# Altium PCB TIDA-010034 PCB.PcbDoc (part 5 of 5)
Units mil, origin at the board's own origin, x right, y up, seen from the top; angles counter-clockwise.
Board outline 4497.63 x 4881.81 mil, 4 copper layers (Top Layer, Signal Layer 1, Signal Layer 2, Bottom Layer), stack 62.18 mil thick; 483 components, 240 nets, 1255 pads, 589 vias.
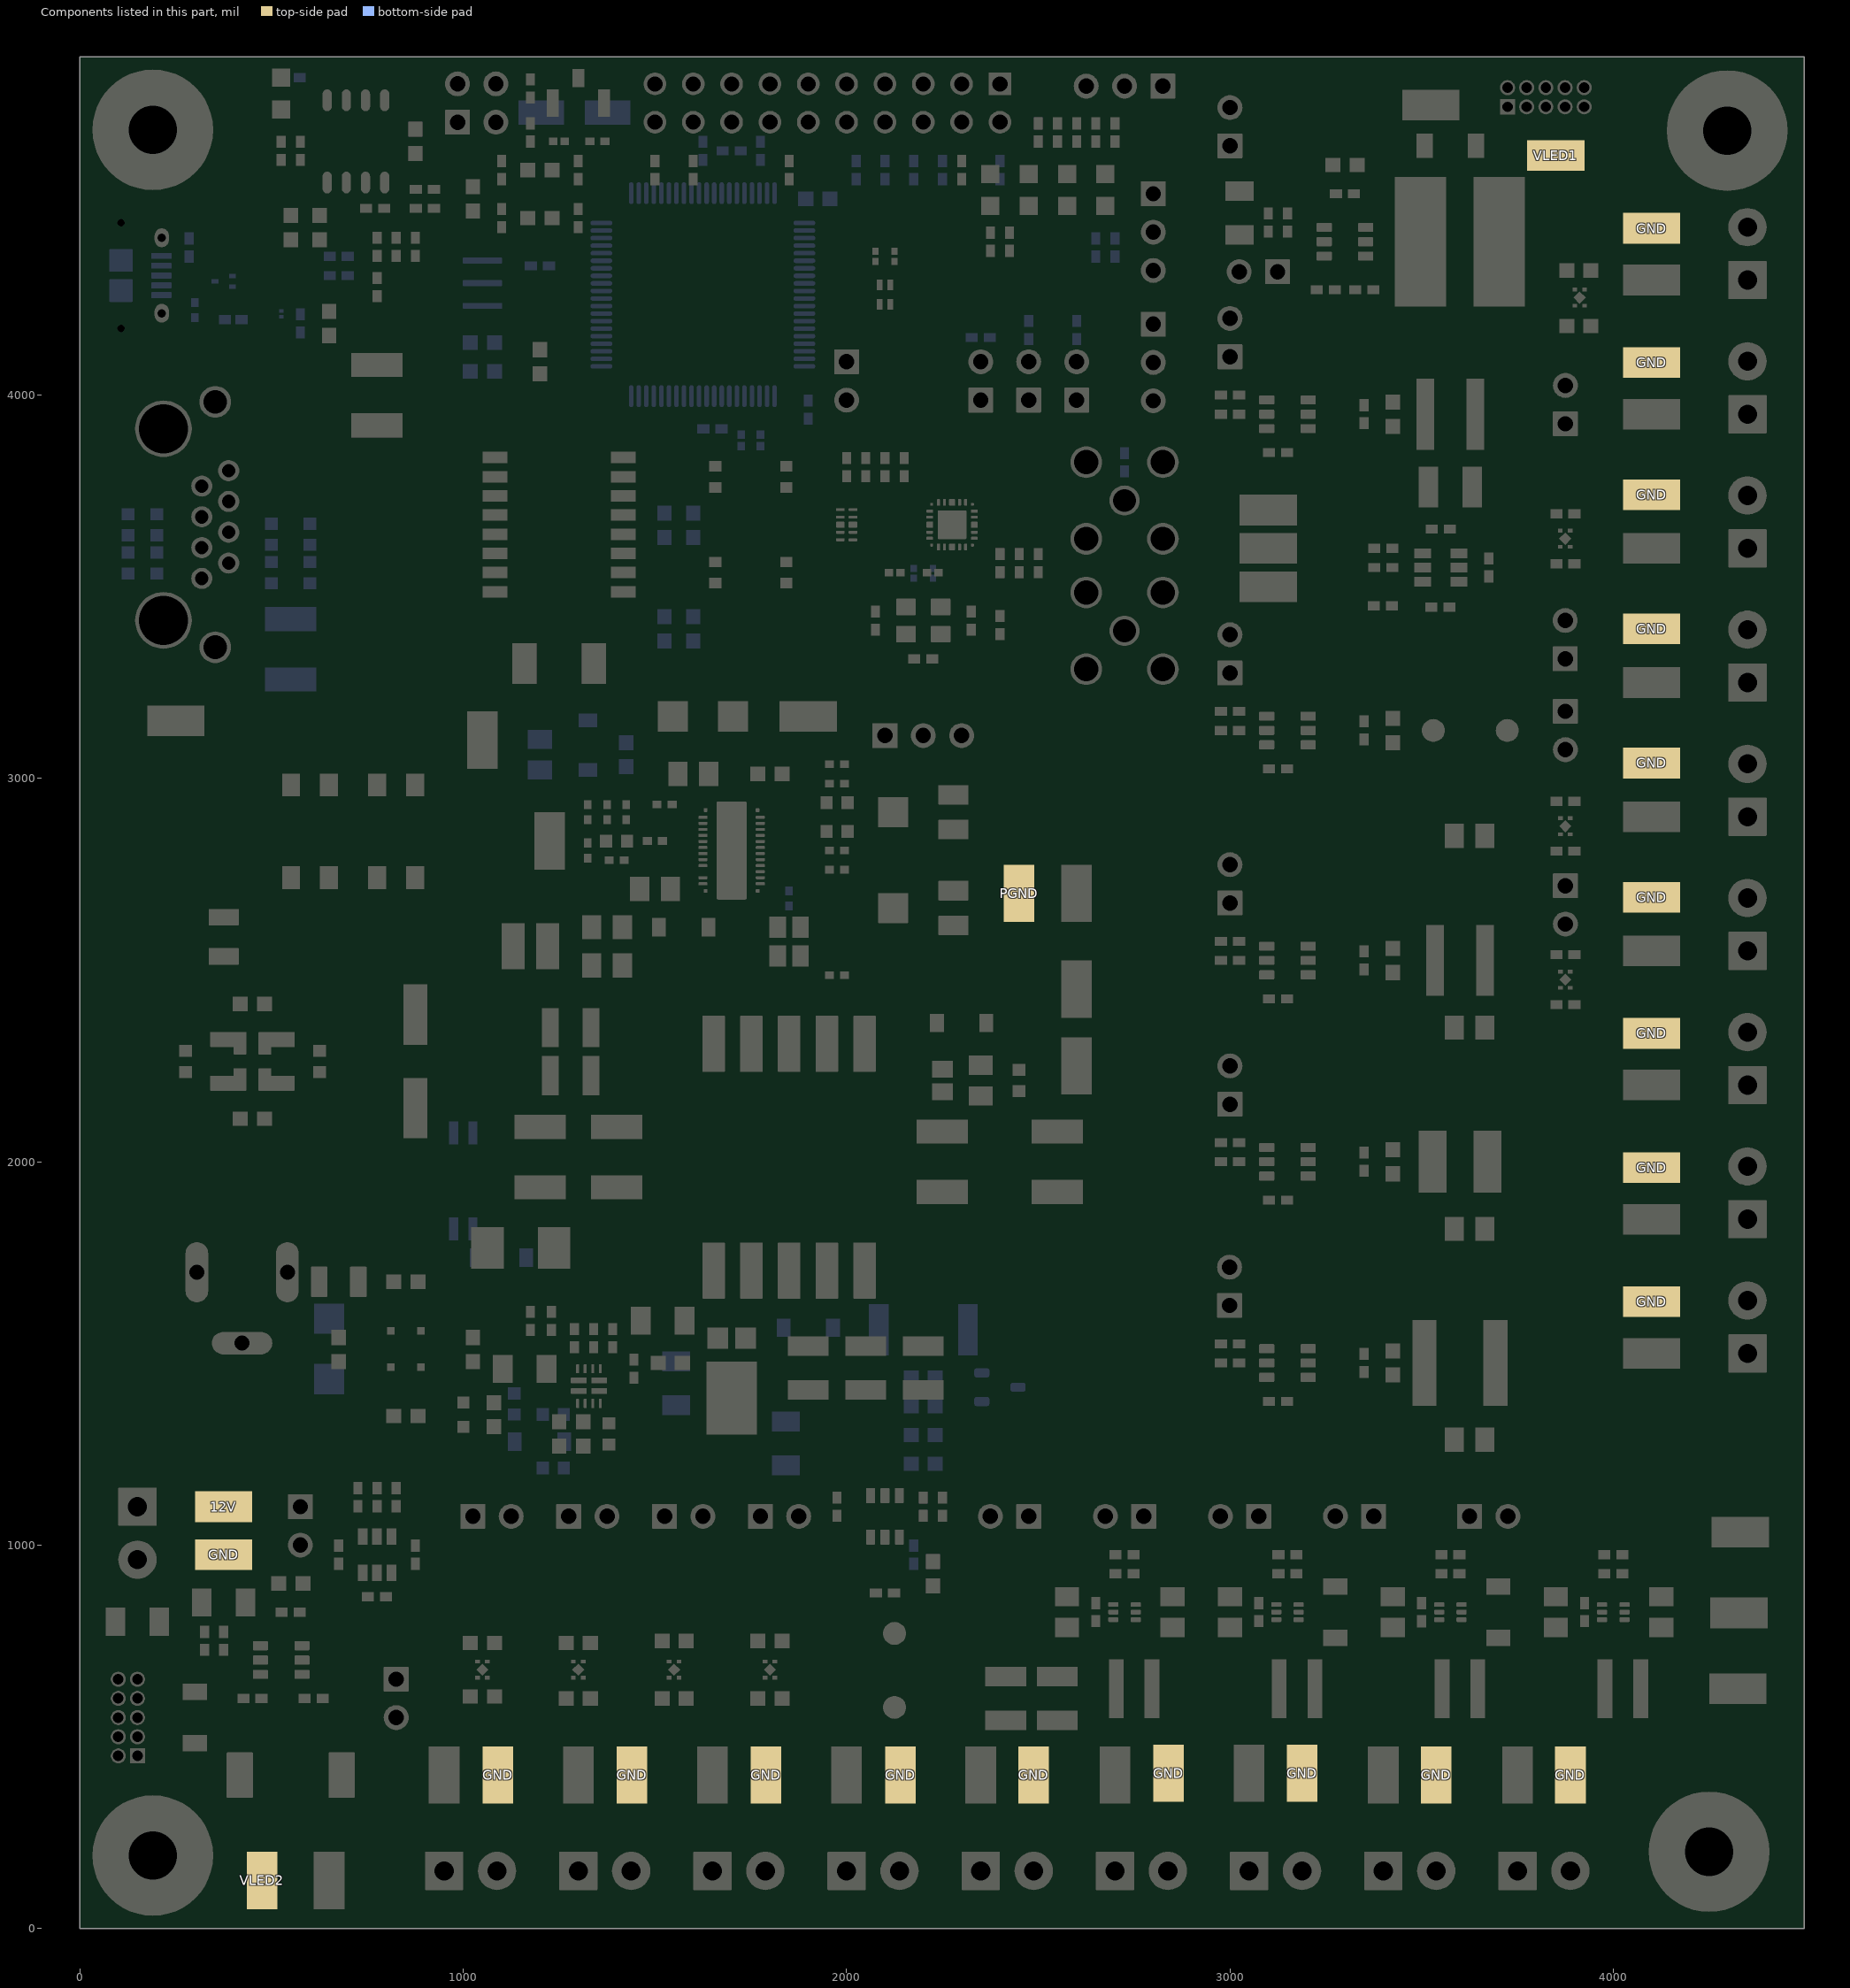
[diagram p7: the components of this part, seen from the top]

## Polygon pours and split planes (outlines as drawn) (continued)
VDD1_1.5V_Img on Signal Layer 2 "Top Layer-No Net 20" (solid, remove dead copper, pour order 568): 4029.76,2622 4410,2622 4420.25,2611.75 4420.25,2502 4410,2492 4029.25,2492 4015,2506.25 4015,2606.87
VDD1_2.8V_Img on Signal Layer 2 "Top Layer-No Net 16" (solid, pour order 566): 3880,2900 3890,2890 3950,2890 3960,2880 4000,2880 4050,2830 4410,2830 4420,2840 4420,2950 4410,2960 3890,2960 3880,2950
NetC76_1 on Signal Layer 2 "Bottom Layer-No Net 2" (solid, pour order 550): 2128,988 2138,978 2138,957 2138,678 2128,668 2068,668 2058,678 2058,978 2068,988
NetC39_1 on Signal Layer 2 "Bottom Layer-No Net 2" (solid, pour order 546): 3240,3980 3250,3990 3580,3990 3590,3980 3590,3920 3580,3910 3250,3910 3240,3920
NetC46_1 on Signal Layer 2 "Bottom Layer-No Net 2" (solid, pour order 536): 3240,3155 3250,3165 3580,3165 3590,3155 3590,3095 3580,3085 3250,3085 3240,3095
EARTH_GND on Signal Layer 2 "Signal Layer 1-No Net 2" (solid, remove dead copper, pour order 352): 30,3980 100,4050 465,4050 553.19,3961.81 878.19,3961.81 930,3910 1215,3910 1215,3250 1195,3230 105,3230 30,3305
VDD1_5V on Signal Layer 2 "Signal Layer 2-No Net 9" (solid, pour order 492): 3560,4132 3580,4152 4178,4152 4190,4140 4190,4030 4210,4010 4410,4010 4420,4000 4420,3850 4410,3840 3687,3840 3687,4020 3580,4020 3560,4040
VDD1_3.3VA on Signal Layer 2 "Top Layer-No Net 20" (solid, remove dead copper, pour order 490): 4029.76,4372 4410,4372 4420.25,4361.75 4420.25,4252 4410,4242 4029.25,4242 4015,4256.25 4015,4356.87
VDD1_3.3V on Signal Layer 2 "Signal Layer 2-No Net" (solid, pour order 482): 20 vertices, not listed, extent 3600,3130 4420,3450
VDD2_5V on Signal Layer 2 "Signal Layer 2-No Net 7" (solid, pour order 444): 17 vertices, not listed, extent 2230,30 2590,600
VDD2_5V on Signal Layer 2 "Signal Layer 2-No Net 5" (solid, pour order 442): 2720,1120 2730,1130 2850,1130 2960,1240 3950,1240 3970,1220 3970,1030 3960,1020 2730,1020 2720,1030
VDD2_5V on Signal Layer 2 "Signal Layer 2-No Net 4" (solid, pour order 438): 970,1140 990,1160 1849,1160 1869,1140 1869,990 1849,970 990,970 970,990
GND on Signal Layer 2 "Signal Layer 2-No Net 6" (solid, remove dead copper, pour order 356): 0,4881.81 0,4157 61,4096 514,4096 580.34,4029.66 890.34,4029.66 980,3940 1285,3940 1285,3925 1285,3250 1305,3230 2855,3230 2902,3277 2902,4842.81 2863,4881.81
PGND on Signal Layer 2 "Signal Layer 2-PGND" (solid, remove dead copper, pour order 354): 30,3065 30,2027 93,1964 2666,1964 2872,2170 2872,3128 2815,3185 150,3185
VLED2 on Signal Layer 2 "Bottom Layer-No Net 8" (solid, remove dead copper, pour order 312): 684.71,775.29 684.71,54.71 665,35 410,35 367,78 367,270 202,435 60,435 30.26,464.74 30,525 30,820 90,880 580,880
12V on Signal Layer 2 "Signal Layer 2-No Net 2" (solid, remove dead copper, pour order 302): 27 vertices, not listed, extent 35,1025 3171,4881
VDD2_3.3V on Signal Layer 2 "Signal Layer 2-No Net 1" (solid, remove dead copper, pour order 298): 2615,770 2625,780 2893.39,780 2901,771.16 2901,40 2891,30 2625,30 2615,40
VDD2_1.5V_Img on Signal Layer 2 "Top Layer-No Net 5" (solid, remove dead copper, pour order 288): 1884,189 1884,39 1892.91,30.09 1987.74,30.26 2052.95,29.95 2063,40 2063,235 2038,260 1853,445 1853,640 1843,650 1753.47,650 1743,639.53 1743,330
VDD2_2.8V_Img on Signal Layer 2 "Top Layer-No Net 9" (solid, pour order 284): 1537,650.28 1664.72,650.28 1675,640 1675,284.28 1722,237.28 1722,40.28 1712,30.28 1532,30.28 1522,40.28 1522,635.28
VDD2_1.8V_Img on Signal Layer 2 "Top Layer-No Net 11" (solid, remove dead copper, pour order 280): 1207,626.94 1215.71,635.65 1386.21,635.65 1397,624.86 1397,529.17 1362,494.17 1362,40.18 1352.33,29.94 1216.76,29.94 1207,40.21
VDD2_3.3VA on Signal Layer 2 "Top Layer-No Net 13" (solid, remove dead copper, pour order 276): 901,470 901,640 911,650 1093.53,650 1104,639.53 1104,328 1036,260 1036,40 1026,30 911.1,30 901,40.1
NetC29_1 on Signal Layer 2 "Bottom Layer-No Net 2" (solid, pour order 506): 3240,2030 3250,2040 3580,2040 3590,2030 3590,1970 3580,1960 3250,1960 3240,1970
NetC38_1 on Signal Layer 2 "Bottom Layer-No Net 2" (solid, pour order 518): 3240,1505 3250,1515 3271,1515 3550,1515 3560,1505 3560,1445 3550,1435 3250,1435 3240,1445
NetC50_1 on Signal Layer 2 "Bottom Layer-No Net 2" (solid, pour order 526): 3240,2555 3250,2565 3580,2565 3590,2555 3590,2495 3580,2485 3250,2485 3240,2495
VLED1 on Signal Layer 2 "vm" (solid, remove dead copper, pour order 626): 3667,4621.6 3677.58,4611.03 3743.03,4611.03 3748,4616 3748,4677 3738,4687 3673.78,4687 3667,4680.22
EARTH_GND on Signal Layer 1 "Signal Layer 1-No Net 2" (solid, remove dead copper, pour order 266): 30,3980 100,4050 465,4050 553.19,3961.81 878.19,3961.81 930,3910 1225,3910 1225,3250 1205,3230 105,3230 30,3305
PGND on Signal Layer 1 "Signal Layer 1-PGND" (solid, remove dead copper, pour order 262): 30,3065 30,2140 165,2005 2620,2005 2775,2160 2775,3050 2640,3185 150,3185
GND on Signal Layer 1 "Signal Layer 1-No Net" (solid, remove dead copper, pour order 258): 20 vertices, not listed, extent 0,0 4945,4880

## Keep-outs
Keep-Out Layer:
  the board outline again, w10
  text ".Layer_Name" at 577,-1346.68 h60

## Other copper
Top Layer:
  region net GND: 3877,2475 3945,2475 3945,2390 3877,2390
  region net GND: 3877,2875 3950,2875 3950,2798 3877,2798
  region net GND: 3873,3625 3873,3710 3792,3710 3792,3625
  region net GND: 3908,4254 3881,4254 3880,4255 3880,4382.5 3907.5,4382.5 3908,4383
  region net GND: 1802,675 1801.81,587 1914.98,587 1914.98,675
  region net GND: 1552,675 1552,600 1561,591 1606,591 1606,675
  region net GND: 1303,675 1303,541.8 1311.23,535.23 1359,541 1374,556 1372,558 1372,675
  region net GND: 1053,675.5 1090.88,675.5 1093,673.38 1093,479.5 1092,480.5 1053,480.5
  pour cut-out: 3538.62,1589 3658,1589 3659,1590 3660,1589 3660,1359.62 3540.38,1359.62 3539,1361 3539,1588
  pour cut-out: 484,560 612.62,560 614,561.38 614,241 487,241 487,246 487,254 487,561
  pour cut-out: 1957.32,710.43 2292.68,710.43 2296,707.11 2296,641 1959,641 1957.32,639.32
  pour cut-out: 3564,4571.13 3636,4571.13 3636,4228.87 3564,4228.87 3564,4286.63 3564,4304.34
  pour cut-out: 3539,4064 3598,4064 3605,4057 3605,3836 3536.71,3836 3533,3839.71 3538.85,3845.56 3538.85,4059.13
  pour cut-out: 3590,3296 3660.43,3296 3660.43,2953.74 3590,2953.74 3590,3011.5 3590,3029.21
  pour cut-out: 3565.15,2112.66 3635.15,2112.66 3635.15,1884.66 3565.15,1884.66 3565,1894.21 3565,2107.79
  pour cut-out: 3560,2639 3637,2639 3637,2411 3560,2411 3560,2441
  pour cut-out: 354,3876 1049,3876 1049,3228 481,3228 481,3272 481,3460 323,3460 276,3507 276,3798
  pour cut-out: 1586.61,2231 1574,2218.39 1574,1814 1597,1791 2108,1791 2124,1807 2124,2206 2099,2231
  pour cut-out: 1473,4752 1393,4672 1393,4527 1596,4324 1596,4132 2022,3706 2312,3706 2318,3700 2318,3625 2312,3619 2252,3619 2247,3614 2247,3562 2253,3556 2253,3506 2295,3464 2358,3464 2374,3480 2374,3556 2383,3565 2522,3565 2555,3598 2555,4149 2337,4367 2337,4738 2323,4752
  pour cut-out: 1865,3866 2022,3709 2223,3709 2232,3700 2232,3623 2226,3617 2058,3617 1907,3466 1826,3466 1817,3475 1817,3861 1822,3866
  text ".Layer_Name" at 577,-1346.68 h60
Signal Layer 1:
  pour cut-out: 3485.52,2115 3709,2115 3709,2098.48 3709,1886 3485.5,1886
  pour cut-out: 3487.52,2641 3711,2641 3711,2624.48 3711,2412 3487.5,2412
  pour cut-out: 3476,1590 3721,1590 3717,1586 3717,1361 3477.97,1361 3475.98,1362.98 3476,1363
  pour cut-out: 1944,848 2308,848 2308.5,847.5 2308,847 2308,501 1943,501 1944,502
  pour cut-out: 354,3876 1049,3876 1049,3386 481,3386 481,3460 323,3460 276,3507 276,3798
  pour cut-out: 3788.44,4564 3788.44,4227 3786.44,4225 3785.44,4226 3426.44,4226 3426.44,4562 3428.44,4564
  pour cut-out: 3464.25,4057.81 3680,4057.81 3680,3834.19 3464.25,3834.19
  pour cut-out: 3452.42,3297.17 3791,3297.17 3791,2942.83 3452.42,2942.83
  pour cut-out: 3930,719.5 4120,719.5 4120,529.5 4119,530.5 3930,530.5
  pour cut-out: 3506,717 3696,717 3696,527 3695,528 3506,528
  pour cut-out: 3079,721 3269,721 3269,531 3268,532 3079,532
  pour cut-out: 2651,722 2841,722 2841,532 2840,533 2651,533
  pour cut-out: 1595,2384 1574,2363 1574,1661 1596,1639 2091,1639 2124,1672 2124,2356 2096,2384
  pour cut-out: 463,568 377,482 377,317 464,230 637,230 723,316 723,480 635,568
  text ".Layer_Name" at 744,-1341 h50
Signal Layer 2:
  rectangle net VDD2_1.1V: 3250,678.92 3300,733
  rectangle net VDD2_1.35V: 3675,678 3735,738
  region net VDD1_1.8V_Img: 3853.35,3704.35 3869,3720 4190,3720 4240,3670 4410,3670 4420,3660 4420,3530 4410,3520 4120,3520 4010,3630 3867.81,3630 3853.35,3644.47
  pour cut-out: 3688,4068 3689,4067 3689,3834 3463,3834 3462,3835 3462,3910 3533,3910 3541,3918 3541,3983 3534,3990 3462,3990 3462,4067 3463,4068
  pour cut-out: 3452,3302 3452.42,3164.88 3580.12,3164.88 3590,3155 3590,3095 3580,3085 3452,3085 3452,2943.25 3452.42,2942.83 3798,2943 3798,3306 3452,3306
  pour cut-out: 3486,2115 3486,2039 3558,2039 3568,2029 3568,1969 3558,1959 3485,1959 3485,1885 3709,1885 3709,2115
  pour cut-out: 3488,2641 3488,2565 3560,2565 3570,2555 3570,2495 3560,2485 3487,2485 3487,2411 3711,2411 3711,2641
  pour cut-out: 3476,1590 3721,1590 3722,1589 3717,1584 3717,1361 3476,1361 3475,1362 3475.98,1362.98 3475.98,1435 3535,1435 3543,1442.2 3543,1507 3535,1515 3476,1515
  pour cut-out: 1944,848 2057,848 2057,723 2069.57,710.43 2125.43,710.43 2138,723 2138,848 2309,848 2308,847 2308,501 1943,501 1944,502
  pour cut-out: 354,3876 1049,3876 1049,3386 481,3386 481,3460 323,3460 276,3507 276,3798
  pour cut-out: 3788.44,4564 3788.44,4227 3786.44,4225 3785.44,4226 3426.44,4226 3426.44,4562 3428.44,4564
  pour cut-out: 3934.45,715.55 4124.45,715.55 4124.45,525.55 4123.45,526.55 3934.45,526.55
  pour cut-out: 3505,719 3695,719 3695,529 3694,530 3505,530
  pour cut-out: 3081,718.5 3271,718.5 3271,528.5 3270,529.5 3081,529.5
  pour cut-out: 2654,718 2844,718 2844,528 2843,529 2654,529
  pour cut-out: 1595,2384 1574,2363 1574,1661 1596,1639 2091,1639 2124,1672 2124,2356 2096,2384
  pour cut-out: 463,568 377,482 377,317 464,230 637,230 723,316 723,480 635,568
  text ".Layer_Name" at 759,-1341 h50
Bottom Layer:
  region net VDD1_1.8V_Img: 3853.35,3704.35 3869,3720 4190,3720 4240,3670 4410,3670 4420,3660 4420,3530 4410,3520 4120,3520 4010,3630 3867.81,3630 3853.35,3644.47
  pour cut-out: 2662,4877 2662,4759.35 2585,4682.35 2585,4275 2606,4296 2755,4296 2757,4298 2755,4300 2755,4579 2899,4723 2899,4872 2666,4872 2660,4878
  pour cut-out: 1448,3912 1581.31,3912 1679,3814.31 1679,3466 1680,3465 1456,3465 1443,3478 1443,3484
  pour cut-out: 3688,4068 3689,4067 3689,3834 3463,3834 3462,3835 3462,3910 3533,3910 3541,3918 3541,3983 3534,3990 3462,3990 3462,4067 3463,4068
  pour cut-out: 3452,3302 3452.42,3164.88 3580.12,3164.88 3590,3155 3590,3095 3580,3085 3452,3085 3452,2943.25 3452.42,2942.83 3798,2943 3798,3306 3452,3306
  pour cut-out: 3486,2115 3486,2039 3558,2039 3568,2029 3568,1969 3558,1959 3485,1959 3485,1885 3709,1885 3709,2115
  pour cut-out: 3488,2641 3488,2565 3560,2565 3570,2555 3570,2495 3560,2485 3487,2485 3487,2411 3711,2411 3711,2641
  pour cut-out: 3476,1590 3721,1590 3722,1589 3717,1584 3717,1361 3476,1361 3475,1362 3475.98,1362.98 3475.98,1435 3535,1435 3543,1442.2 3543,1507 3535,1515 3476,1515
  pour cut-out: 1944,848 2057,848 2057,723 2069.57,710.43 2125.43,710.43 2138,723 2138,848 2309,848 2308,847 2308,501 1943,501 1944,502
  pour cut-out: 354,3876 1049,3876 1049,3386 481,3386 481,3460 323,3460 276,3507 276,3798
  pour cut-out: 3792,4569 3792,4232 3790,4230 3789,4231 3430,4231 3430,4567 3432,4569
  pour cut-out: 3934.45,715.55 4124.45,715.55 4124.45,527.55 4123.45,526.55 3934.45,526.55
  pour cut-out: 3505,718.07 3695,718.07 3695,530.07 3694,529.07 3505,529.07
  pour cut-out: 3081,718.5 3271,718.5 3271,530.5 3270,529.5 3081,529.5
  pour cut-out: 2654,717 2844,717 2844,529 2843,528 2654,528
  pour cut-out: 1595,2384 1574,2363 1574,1661 1596,1639 2091,1639 2124,1672 2124,2356 2096,2384
  pour cut-out: 463,568 377,482 377,317 464,230 637,230 723,316 723,480 635,568
  pour cut-out: 1703,3872 1703,3824 1748,3779 1826,3779 2292,3313 2509,3313 2575,3379 2575,3890 2671,3986 2671,4403 2628,4446 2593,4446 2438,4601 2438,4730 2427,4741 1770,4741 1760,4731 1760,4692 1821,4631 1960,4631 1982,4609 1982,4529 2019,4492 2019,4233 1948,4162 1948,4034 1957,4025 2124,4025 2293,3856 2293,3773 2316,3750 2316,3620 2286,3590 2138,3590 1856,3872
  region net NetC57_2: 483.12,3526.1 478.67,3521.65 478.67,3421 500.34,3399.33 610.33,3399.33 622.62,3411.62 622.62,3522.08 618.6,3526.1
  text ".Layer_Name" at 577,-1346.68 h60
Multi-Layer:
  pour cut-out: 1448,3608 1448,3466 1862,3466 1862,3608
  pour cut-out: 1453,3866 1863,3866 1863,3717 1453,3717
  pour cut-out: 997,3925 997,3410 1455,3410 1455,3925

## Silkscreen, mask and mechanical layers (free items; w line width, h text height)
Top Overlay:
  circle w5: c1396,4623 r20
  circle w5: c1646.71,4070.48 r20
  region: 32,2421 32,2121 132,2121 132,2421
  lines w6: 0,4117 1065,4117 1071,4111 1071,3911 1072,3910 ; 2,1222 2915,1222 ; 310,2165 315,2165 330,2180 ; 380,645 380,642.44 400.79,621.65 ; 810,4235 825,4235 ; 825,575 825,655 ; 905,4335 905,4330 930,4305 945,4305 ; 955,4485 960,4485 970,4475 970,4460 ; 955,4535 960,4535 975,4550 975,4560 ; 1050,4605 1050,4595 1060,4585 1070,4585 ; 1250,3276.81 1250,3911.79 ; 1250,3280.31 1250,3242.93 ; 1302,1585.84 1302,1676.26 1321,1695.26 ; 1372,4719.34 1390.01,4701.33 1390.01,4700.99 1413,4678 1414,4677 1414,4676 1434.06,4655.94 1434.06,4504.94 1456,4483 1474,4483 ; 1447.24,2857.48 1455,2865.24 1455,2870 ; 1472,1401 1472,1406 1472,1384.85 1529.27,1327.58 1529.27,1294 ; 1495,2803 1495,2817 ; 1500,2950 1500,2960 ; 1868,619.69 1879.5,619.69 ; 2070,3490 2110,3490 2125,3475 ; 2153.31,3575 2153.31,3564.98 2175.29,3543 2187.12,3543 ; 2191,1148 2191,1157 2206,1172 2213,1172 ; 2360,3111 2412,3111 ; 2400,2275 2415,2290 2420,2290 ; 2402,4662 2426,4638 2426,4631 ; 2465,3620 2475,3630 ; 2476.55,4744 2476.55,4771.83 2510.72,4806 ; 2652.85,4411.81 2666.66,4425.62 2666.66,4443 ; 2885,4805 2920,4840 2930,4840 ; 2914,1551 2914,1223 2915,1222 ; 2915,1636 2915,3787.81 2915,4880.81 2916,4881.81 ; 2925,3239 2502,3238.81 1952,3238.81 1254.12,3238.81 1250,3242.93 ; 2955,1390 2955,1451.5 ; 2960,1905 2960,1978.35 ; 2960,2440 2960,2501 ; 2960,3030 2960,3105 ; 2965,3870 2965,3925 ; 3150,4265 3150,4205 3150,4190 3170,4170 ; 3190.75,3444.29 3215,3420.04 3215,3410 ; 3197,4611 3197,4547 ; 4499,1222 2958,1222 2915,1222 ; 1250,3242.93 1250,3242.93 ; 3197,4547 3187,4557 3205,4557 3197,4549 3197,4547
  text "12V-->PoLs" at 3113,4833 h30
  text "Power Tree" at 3113,4792 h30
  text "A" at 1388,4612 h25
  text "RX_D1" at 2440,4495 h30 r90
  text "CRS_DV" at 2010,4471 h30 r90
  text "PWDN" at 1615,4415 h30 r90
  text "RX_D0" at 2215,4412 h30 r90
  text "TX_D0" at 2111,4405 h30 r90
  text "TX_EN" at 1918,4404 h30 r90
  text "RX_ER" at 1817,4386 h30 r90
  text "TX_D1" at 2312,4386 h30 r90
  text "LED_0" at 2735,4263 h30 r90
  text "PWM INPUT" at 3180,4135 h30
  text "A" at 1638.71,4059.48 h25
  text "LED_2" at 2735,3995 h30 r90
  text "RX_D0" at 2202.47,3989 h30 r90
  text "RX_D1" at 2285,3985 h30 r90
  text "RX_ER" at 1935,3970 h30 r90
  text "CRS_DV" at 2125,3955 h30 r90
  text "CLKOUT" at 2681,3881 h30
  text "PoE Input" at 660,3660 h30
  text "REF_CLK" at 2653,3540 h30
  text "DP83825 Ethernet PHY" at 1413,3259 h30
  text "Dither Control" at 2425,3097 h30
  text "TPS23755" at 31,2881 h30
  text "Powered Device" at 32,2833 h30
  text "Section" at 32,2782 h30
  text "500mA Fuse" at 432,2572 h30
  text "2A Fuse" at 592,1797 h30
  text "TIDA-010034_E1" at 2168,1791 h50
  text "12V Adapter Input" at 43,1440 h30
  text "12V-->5V-->PoLs" at 3898,1174 h30
  text "Power Tree" at 3954,1128 h30
  text "PWM INPUT" at 700,710 h30
  text ".Layer_Name" at 577,-1346.68 h60
Bottom Overlay:
  lines w6: 1657,4732 1657,4681 1668,4670 1668,4664
  text ".Layer_Name" at 577,-1346.68 h60
Top Paste:
  text ".Layer_Name" at 577,-1346.68 h60
Bottom Paste:
  text ".Layer_Name" at 577,-1346.68 h60
Top Solder:
  text ".Layer_Name" at 577,-1346.68 h60
  text ".Layer_Name" at 577,-1346.68 h60
Bottom Solder:
  text ".Layer_Name" at 577,-1346.68 h60
Drill Guide:
  text ".Layer_Name" at 577,-1346.68 h60
M1 Board Outline:
  the board outline again, w10
M2 Board Dimensions:
  rectangle: 0,-763.19 125,-638.19
  rectangle: 125,-888.19 500,-763.19
  lines w7: 0,-763.19 1000,-763.19 ; 125,-888.19 125,-638.19 ; 250,-888.19 250,-638.19 ; 500,-888.19 500,-638.19 ; 750,-888.19 750,-638.19 ; 0,-888.19 1000,-888.19 1000,-638.19 0,-638.19 0,-888.19
M3 3D STEP Top:
  text ".Layer_Name" at 577,-1346.68 h60
M4 3D STEP Bottom:
  text ".Layer_Name" at 577,-1346.68 h60
M5 Assembly Top:
  lines w6: 3124,3759 3154,3789 3191,3789 ; 3250,3494 3280,3524 3280,3642
  lines w10: -292,-1418.36 6308,-1418.36 ; -292,-1215.02 6310,-1215.02 ; -292,-1011.69 -292,-1621.69 3713,-1621.69 6310,-1621.69 6310,-1011.69 -291.5,-1011.69 -291.5,-1621.69 1284,-1621.69 ; 2173,-1621.69 2173,-1011.69 ; 3440,-1215.02 3440,-1011.69 ; 4280,-1215.02 4280,-1011.69 ; 4902,-1628.19 4902,-1425.36
  text "COMPONENTS MARKED 'DNP' SHOULD NOT BE POPULATED." at 1153.5,-806.69 h60
  text "ASSEMBLY VARIANT:" at 1153,-922.19 h60
  text ".VariantName" at 2189,-922.19 h60
  text "PCB VIEWED FROM TOP SIDE" at -228.5,-1143.86 h60
  text "BOARD #:" at 2248,-1143.86 h60
  text ".PRJ_Number" at 2793.5,-1143.86 h60
  text "REV:" at 3638,-1143.86 h60
  text ".PCB_Rev" at 3929.5,-1143.86 h60
  text "SVN REV:" at 4476,-1143.86 h60
  text ".VersionControl_RevNumber" at 4982,-1143.86 h60
  text "TID #:" at 2248,-1347.19 h60
  text ".TID" at 2793.5,-1347.19 h60
  text "'.Layer_Name'" at 219,-1353 h70
  text "PLOT NAME =" at -228.5,-1552.52 h60
  text ".plot_File_Name" at 577,-1552.52 h60
  text "GENERATED    :" at 2250,-1552.52 h60
  text ".Print_Date" at 3119.5,-1552.52 h60
  text ".Print_Time" at 3848.5,-1552.52 h60
  text "TEXAS INSTRUMENTS" at 5113,-1552.52 h60
M6 Assembly Bottom:
  lines w10: -292.5,-1215.52 6309.5,-1215.52 ; -290.5,-1418.86 6309.5,-1418.86 ; 1115.5,-1628.69 1115.5,-1425.86 ; 1737.5,-1215.52 1737.5,-1012.19 ; 2577.5,-1215.52 2577.5,-1012.19 ; 3844.5,-1622.19 3844.5,-1012.19 ; 4733.5,-1622.19 6309,-1622.19 6309,-1012.19 -292.5,-1012.19 -292.5,-1622.19 2304.5,-1622.19 6309.5,-1622.19 6309.5,-1012.19
  text "COMPONENTS MARKED 'DNP' SHOULD NOT BE POPULATED." at 6102,-806.19 h60
  text ".VariantName" at 5058,-922.19 h60
  text "ASSEMBLY VARIANT:" at 6097,-922.19 h60
  text ".VersionControl_RevNumber" at 1035.5,-1144.36 h60
  text "SVN REV:" at 1541.5,-1144.36 h60
  text ".PCB_Rev" at 2088,-1144.36 h60
  text "REV:" at 2379.5,-1144.36 h60
  text ".PRJ_Number" at 3224,-1144.36 h60
  text "BOARD #:" at 3769.5,-1144.36 h60
  text "PCB VIEWED FROM BOTTOM SIDE" at 6246,-1144.36 h60
  text ".TID" at 3224,-1347.69 h60
  text "TID #:" at 3769.5,-1347.69 h60
  text "'.Layer_Name'" at 5845,-1347.69 h70
  text "TEXAS INSTRUMENTS" at 904.5,-1553.02 h60
  text ".Print_Time" at 2169,-1553.02 h60
  text ".Print_Date" at 2898,-1553.02 h60
  text "GENERATED    :" at 3767.5,-1553.02 h60
  text ".plot_File_Name" at 5440.5,-1553.02 h60
  text "PLOT NAME =" at 6246,-1553.02 h60
M9 Title Sheet:
  drawing of 57 lines, arcs and shapes, not listed
  text "1" at 739.84,7548.31 h70
  text "2" at 3235.5,7548.31 h70
  text "3" at 5724.84,7548.31 h70
  text "4" at 8231.51,7548.31 h70
  text "5" at 10730.5,7548.31 h70
  text "6" at 13235.5,7548.31 h70
  text "A" at -416.5,6405.31 h70
  text "A" at 14383.5,6405.31 h70
  text "B" at -416.5,4025.31 h70
  text "B" at 14383.5,4025.31 h70
  text "C" at -416.5,1650.31 h70
  text "C" at 14383.5,1650.31 h70
  text "PROJECT TITLE:" at 11343.5,-210.69 h45
  text ".PRJ_Title" at 11393.5,-344.02 h70
  text "DESIGNED FOR:" at 11343.5,-511.69 h45
  text ".PRJ_Customer" at 11393.5,-651.69 h70
  text "D" at -416.5,-719.69 h70
  text "D" at 14383.5,-719.69 h70
  text "FILE NAME:" at 11343.5,-811.69 h45
  text ".PCB_File_Name_No_Path" at 11393.5,-931.69 h70
  text "Texas Instruments (TI) and/or its licensors do not warrant the accuracy or completeness of this specification" at 6374,-1093.53 h45
  text "ENGINEER:" at 11343.5,-1101.69 h45
  text "LAYOUT BY:" at 12848.5,-1101.69 h45
  text "or any information contained therein. TI and/or its licensors do not warrant that this design will meet" at 6329.01,-1206.19 h45
  text ".PRJ_Engineer" at 11393.5,-1256.68 h70
  text ".PCB_Layout" at 12899,-1256.68 h70
  text "the specifications, will be suitable for your application or fit for any particular purpose, or will operate in" at 6329.01,-1318.86 h45
  text "ALTIUM DESIGNER VERSION:" at 12848.5,-1411.69 h45
  text "an implementation. TI and/or its licensors do not warrant that the design is production worthy. You should" at 6329.01,-1431.52 h45
  text "completely validate and test your design implementation to confirm the system functionality for your application." at 6374,-1544.19 h45
  text ".print_Scale" at 11393.5,-1545.02 h70
  text ".Application_BuildNumber" at 12899,-1545.02 h70
  text "1" at 739.84,-1751.69 h70
  text "2" at 3235.5,-1751.69 h70
  text "3" at 5724.84,-1751.69 h70
  text "4" at 8231.51,-1751.69 h70
  text "5" at 10730.5,-1751.69 h70
  text "6" at 13235.5,-1751.69 h70
M10 Fab Notes:
  drawing of 189 lines, arcs and shapes, not listed
  text "DESIGN INFORMATION" at 12382.02,5867.99 h60
  text "MIN. TRACK WIDTH:" at 11737.46,5735.86 h60
  text "5" at 12833.7,5735.86 h60
  text "MIL" at 12988.46,5735.86 h60
  text "5.906" at 12666,5623 h60
  text "MIN. CLEARANCE:" at 11737.46,5611.73 h60
  text "MIL" at 12988.46,5611.73 h60
  text "18" at 12802,5489 h60
  text "MIN. VIA PAD SIZE:" at 11737.46,5487.61 h60
  text "MIL" at 12988.46,5487.61 h60
  text "0.05mm (2MIL)" at 12432.46,5357.71 h60
  text "MINIMUM ANNULAR RING" at 11408.23,5349.49 h60
  text "EXTERNAL" at 13140.46,5349.49 h60
  text "PER" at 11608.23,5239.36 h60
  text "IPC-D-275 CLASS 2 LEVEL C" at 11828.23,5239.36 h60
  text "MIL, HOLES" at 13316.46,5138.88 h60
  text "+/-" at 12924,5130.29 h60
  text "+/-" at 13778,5130.29 h60
  text "REGISTRATION TOLERANCES:" at 11408.23,5129.23 h60
  text "METAL" at 12608,5129.23 h60
  text "5" at 13184.2,5129.23 h60
  text "3" at 14017.2,5129.23 h60
  text "MIL" at 14133.46,5129.23 h60
  text "HOLE SIZE TOLERANCE (UNLESS OTHERWISE SPECIFIED):" at 11408.23,5030.91 h60
  text "+/-" at 13778,5028.04 h60
  text "3" at 14017.2,5026.98 h60
  text "MIL" at 14133.46,5026.98 h60
  text "MATERIAL:" at 11333.46,4889.33 h60
  text "FR-4 High Tg" at 12319.9,4760.81 h60
  text "X" at 11601,4752.95 h60
  text "FR-4" at 11754.46,4748.3 h60
  text "OTHER" at 13242.46,4748.3 h60
  text "62 MIL (1.6mm) +/-10%" at 12074.56,4605.27 h60
  text "X" at 11954.46,4602.82 h60
  text "THICKNESS:" at 11408.23,4597.05 h60
  text "OTHER" at 13359.46,4597.05 h60
  text "TOLERANCE:" at 11408.23,4458.73 h60
  text "X" at 12256.46,4458.73 h60
  text "ANSI IPC-6012 TYPE 3 CLASS 2" at 12434.48,4458.73 h60
  text "OTHER +/-" at 12434.46,4314.54 h60
  text "BOW & TWIST:" at 11408.23,4169.36 h60
  text "X" at 12256.46,4169.36 h60
  text "ANSI IPC-6012 TYPE 3 CLASS 2" at 12434.48,4169.36 h60
  text "OTHER +/-" at 12434.46,4022.66 h60
  text "DRILLING:" at 11333.46,3892.04 h60
  text "NC_DRILL FILES" at 13094.46,3786.85 h60
  text "REFERENCE:" at 11408.23,3782.91 h60
  text "X" at 12065.46,3782.82 h60
  text "AS SHOWN" at 12243.46,3782.91 h60
  text "X" at 12966.46,3782.91 h60
  text "OTHER" at 13392.46,3640.66 h60
  text "PTH COPPER THICKNESS:" at 11407.91,3637.13 h60
  text "X" at 12547.14,3637.13 h60
  text "20-30 um" at 12675.14,3637.13 h60
  text "BOARD FINISH:" at 11333.46,3489.54 h60
  text "SILKSCREEN:" at 11488.68,3379.41 h60
  text "X" at 12446.46,3379.41 h60
  text "TOP" at 12563.46,3379.41 h60
  text "X" at 12956.46,3379.41 h60
  text "BOTTOM" at 13074.46,3379.41 h60
  text "SILKSCREEN COLOR:" at 11488.68,3224.22 h60
  text "X" at 12445.46,3224.22 h60
  text "WHITE" at 12563.46,3224.22 h60
  text "OTHER" at 13074.46,3224.22 h60
  text "X" at 12576.46,3080.77 h60
  text "GREEN" at 12694.46,3080.77 h60
  text "OTHER" at 13312.46,3080.77 h60
  text "SOLDER RESIST COLOR:" at 11488.68,3073.91 h60
  text "X" at 12576.46,2926.52 h60
  text "MATTE" at 12694.46,2926.52 h60
  text "SEMI-GLOSS" at 13312,2925.88 h60
  text "IMMERSION GOLD (ENIG)" at 12394.46,2753.75 h60
  text "ENEPIG" at 13732,2746.53 h60
  text "SURFACE FINISH:" at 11333.46,2745.53 h60
  text "X" at 12216.46,2745.53 h60
  text "IMM. TIN/SILVER OR EQUIV" at 11663,2608.21 h60
  text "OTHER" at 13094.46,2604.28 h60
  text "ARRAY/PANEL:" at 11333.46,2448.9 h60
  text "CUT AND TRIM PER M1 BOARD OUTLINE" at 12394.46,2440.68 h60
  text "X" at 12212,2438 h60
  text "N.C. ROUTE" at 12394.46,2304.71 h60
  text "V. SCORE" at 13260.46,2304.71 h60
  text "CERTIFICATION:" at 11333.46,2175.58 h60
  text "MATERIALS AND WORKMANSHIP FOR ALL PCBS" at 12058.46,2175.58 h60
  text "TO MEET OR EXCEED THE REQUIREMENTS OF:" at 12058.46,2081.52 h60
  text "X" at 11695.97,1952.89 h60
  text "ANSI IPC-A-600F CLASS ->" at 11823.96,1952.89 h60
  text "X" at 13471.97,1952.89 h60
  text "2" at 13581.96,1952.89 h60
  text "1" at 13266.96,1951.39 h60
  text "3" at 13935.96,1951.39 h60
  text "X" at 12507.97,1805.21 h60
  text "RoHS" at 12635.96,1805.21 h60
  text "OTHER" at 13280.36,1805.21 h60
  text "PER ORDER" at 13677.42,1805.21 h60
  text "ALL BOARDS MUST MEET OR EXCEED UL94-V0 REQUIREMENTS." at 11361,1651.38 h60
  text "PCB MUST BEAR THE UL94V-0 UL REGISTERED MATERIAL ID NUMBER" at 11361,1535.31 h60
  text "ADDITIONAL REQUIREMENTS:" at 11333.46,1365.89 h60
  text "MICROSECTION:" at 11408.23,1258.76 h60
  text "YES" at 12313.96,1258.76 h60
  text "REQUIRED" at 13175.46,1114.43 h60
  text "BARE BOARD ELEC. TEST:" at 11408.23,1111.58 h60
  text "NONE" at 12713.96,1111.58 h60
  text "X" at 13057.46,1111.58 h60
  text "PER ORDER" at 13767.46,1111.58 h60
  text "XX MIL VIAS REQUIRE NON-CONDUCTIVE FILL AND PLANARIZE" at 11576.38,906.63 h59
  text "XX MIL VIAS REQUIRE CONDUCTIVE FILL AND PLANARIZE" at 11584.38,802.65 h60
  text "OUTER XX MIL VIAS REQUIRE 50 OHM SINGLE-ENDED IMPEDANCE" at 11583.39,639.27 h58
  text "LAYER 2 & 3 (INNER LAYERS) XX MIL WIDE, XX MIL SPACE / TRACES REQUIRE 100 OHM DIFFERENTIAL IMPEDANCE" at 11575.39,403.56 h60
M11 Gerber Information:
  lines w10: -292,-1418.36 6308,-1418.36 ; -292,-1215.02 6310,-1215.02 ; -292,-1011.69 -292,-1621.69 3713,-1621.69 6310,-1621.69 6310,-1011.69 -291.5,-1011.69 -291.5,-1621.69 1284,-1621.69 ; 2173,-1621.69 2173,-1011.69 ; 3440,-1215.02 3440,-1011.69 ; 4280,-1215.02 4280,-1011.69 ; 4902,-1628.19 4902,-1425.36
  text "ALL ARTWORK VIEWED FROM TOP SIDE" at -228.5,-1143.86 h60
  text "BOARD #:" at 2248,-1143.86 h60
  text ".PRJ_Number" at 2793.5,-1143.86 h60
  text "REV:" at 3638,-1143.86 h60
  text ".PCB_Rev" at 3929.5,-1143.86 h60
  text "SVN REV:" at 4476,-1143.86 h60
  text ".VersionControl_RevNumber" at 4982,-1143.86 h60
  text "LAYER NAME =" at -228.5,-1346.68 h60
  text "TID #:" at 2248,-1347.19 h60
  text ".TID" at 2793.5,-1347.19 h60
  text "PLOT NAME =" at -228.5,-1552.52 h60
  text ".plot_File_Name" at 577,-1552.52 h60
  text "GENERATED    :" at 2250,-1552.52 h60
  text ".Print_Date" at 3119.5,-1552.52 h60
  text ".Print_Time" at 3848.5,-1552.52 h60
  text "TEXAS INSTRUMENTS" at 5113,-1552.52 h60
M12 Stackup:
  drawing of 295 lines, arcs and shapes, not listed
  text "Layer" at 9797.84,7341.81 h60
  text "Name" at 10207.76,7341.81 h60
  text "Material" at 11147.5,7341.81 h60
  text "Thickness" at 12007.26,7341.81 h60
  text "Constant" at 12657.1,7341.81 h60
  text "Board Layer Stack" at 13226.96,7341.81 h60
  text "1" at 9797.84,7221.81 h60
  text "Top Overlay" at 10207.76,7221.81 h60
  text "2" at 9797.84,7101.81 h60
  text "Top Solder" at 10207.76,7101.81 h60
  text "Solder Resist" at 11147.5,7101.81 h60
  text "0.40mil" at 12007.26,7101.81 h60
  text "3.5" at 12657.1,7101.81 h60
  text "3" at 9797.84,6981.81 h60
  text "Top Layer" at 10207.76,6981.81 h60
  text "Copper" at 11147.5,6981.81 h60
  text "1.89mil" at 12007.26,6981.81 h60
  text "4" at 9797.84,6861.81 h60
  text "Dielectric1" at 10207.76,6861.81 h60
  text "FR-4" at 11147.5,6861.81 h60
  text "4.20mil" at 12007.26,6861.81 h60
  text "4.8" at 12657.1,6861.81 h60
  text "5" at 9797.84,6741.81 h60
  text "Signal Layer 1" at 10207.76,6741.81 h60
  text "Copper" at 11147.5,6741.81 h60
  text "1.38mil" at 12007.26,6741.81 h60
  text "6" at 9797.84,6621.81 h60
  text "Dielectric 2" at 10207.76,6621.81 h60
  text "FR-4" at 11147.5,6621.81 h60
  text "47.24mil" at 12007.26,6621.81 h60
  text "4.8" at 12657.1,6621.81 h60
  text "7" at 9797.84,6501.81 h60
  text "Signal Layer 2" at 10207.76,6501.81 h60
  text "Copper" at 11147.5,6501.81 h60
  text "1.38mil" at 12007.26,6501.81 h60
  text "8" at 9797.84,6381.81 h60
  text "Dielectric 3" at 10207.76,6381.81 h60
  text "FR-4" at 11147.5,6381.81 h60
  text "4.20mil" at 12007.26,6381.81 h60
  text "4.8" at 12657.1,6381.81 h60
  text "9" at 9797.84,6261.81 h60
  text "Bottom Layer" at 10207.76,6261.81 h60
  text "Copper" at 11147.5,6261.81 h60
  text "1.89mil" at 12007.26,6261.81 h60
  text "10" at 9797.84,6141.81 h60
  text "Bottom Solder" at 10207.76,6141.81 h60
  text "Solder Resist" at 11147.5,6141.81 h60
  text "0.40mil" at 12007.26,6141.81 h60
  text "3.5" at 12657.1,6141.81 h60
  text "11" at 9797.84,6021.81 h60
  text "Bottom Overlay" at 10207.76,6021.81 h60
M13 Component Bodies Top:
  text ".Layer_Name" at 577,-1346.68 h60
M14 Component Bodies Bottom:
  text ".Layer_Name" at 577,-1346.68 h60
M15 Courtyards Top:
  text ".Layer_Name" at 577,-1346.68 h60
M16 Courtyards Bottom:
  text ".Layer_Name" at 577,-1346.68 h60
Drill Drawing:
  circle w10: c4951.62,4617.27 r20
  circle w10: c4951.62,4617.27 r33.33
  circle w10: c4951.62,3717.27 r33.33
  lines w10: 4918.29,2350.61 4934.96,2350.61 4934.96,2333.94 4968.29,2333.94 4968.29,2350.61 4984.96,2350.61 4984.96,2383.94 4968.29,2383.94 4968.29,2400.61 4934.96,2400.61 4934.96,2383.94 4918.29,2383.94 4918.29,2350.61 ; 4918.29,2700.61 4984.96,2700.61 4951.62,2633.94 4918.29,2700.61 ; 4918.29,2783.94 4951.62,2800.61 4984.96,2783.94 4968.29,2817.27 4984.96,2850.61 4951.62,2833.94 4918.29,2850.61 4934.96,2817.27 4918.29,2783.94 ; 4918.29,2950.61 4934.96,2950.61 4951.62,2933.94 4968.29,2950.61 4984.96,2950.61 4968.29,2967.27 4984.96,2983.94 4968.29,2983.94 4951.62,3000.61 4934.96,2983.94 4918.29,2983.94 4934.96,2967.27 4918.29,2950.61 ; 4918.29,3150.61 4984.96,3150.61 4951.62,3083.94 4918.29,3150.61 ; 4918.29,3233.94 4984.96,3233.94 4984.96,3300.61 4918.29,3300.61 4918.29,3233.94 ; 4918.29,3533.94 4918.29,3550.61 4934.96,3567.27 4918.29,3583.94 4918.29,3600.61 4934.96,3600.61 4951.62,3583.94 4968.29,3600.61 4984.96,3600.61 4984.96,3583.94 4968.29,3567.27 4984.96,3550.61 4984.96,3533.94 4968.29,3533.94 4951.62,3550.61 4934.96,3533.94 4918.29,3533.94 ; 4918.29,3983.94 4918.29,4000.61 4934.96,4017.27 4918.29,4033.94 4918.29,4050.61 4934.96,4050.61 4951.62,4033.94 4968.29,4050.61 4984.96,4050.61 4984.96,4033.94 4968.29,4017.27 4984.96,4000.61 4984.96,3983.94 4968.29,3983.94 4951.62,4000.61 4934.96,3983.94 4918.29,3983.94 ; 4918.29,4150.61 4934.96,4150.61 4951.62,4133.94 4968.29,4150.61 4984.96,4150.61 4968.29,4167.27 4984.96,4183.94 4968.29,4183.94 4951.62,4200.61 4934.96,4183.94 4918.29,4183.94 4934.96,4167.27 4918.29,4150.61 ; 4918.29,4433.94 4984.96,4433.94 4984.96,4500.61 4918.29,4500.61 4918.29,4433.94 ; 4918.29,4917.27 4951.62,4883.94 4984.96,4917.27 4951.62,4950.61 4918.29,4917.27 ; 4931.62,2687.27 4971.62,2687.27 4951.62,2647.27 4931.62,2687.27 ; 4931.62,2957.27 4941.62,2957.27 4951.62,2947.27 4961.62,2957.27 4971.62,2957.27 4961.62,2967.27 4971.62,2977.27 4961.62,2977.27 4951.62,2987.27 4941.62,2977.27 4931.62,2977.27 4941.62,2967.27 4931.62,2957.27 ; 4931.62,3547.27 4931.62,3557.27 4941.62,3567.27 4931.62,3577.27 4931.62,3587.27 4941.62,3587.27 4951.62,3577.27 4961.62,3587.27 4971.62,3587.27 4971.62,3577.27 4961.62,3567.27 4971.62,3557.27 4971.62,3547.27 4961.62,3547.27 4951.62,3557.27 4941.62,3547.27 4931.62,3547.27 ; 4931.62,4447.27 4971.62,4447.27 4971.62,4487.27 4931.62,4487.27 4931.62,4447.27
  lines w15: 4858.5,2288.94 9801.16,2288.94 ; 4858.5,5138.94 9801.16,5138.94 ; 5409.38,2138.94 5409.38,5288.94 ; 6009.22,2138.94 6009.22,5288.94 ; 7158.88,2138.94 7158.88,5288.94 ; 7664.76,2138.94 7664.76,5288.94 ; 8398.56,2138.94 8398.56,5288.94 ; 4858.5,2138.94 9801.16,2138.94 9801.16,5288.94 4858.5,5288.94 4858.5,2138.94
  text "Impedance Details:" at 5761,6888 h70
  text "Outer layers 50ohm 6 mil Trace width" at 5761,6668 h70
  text "For outer layers and layer 3 100 ohm 5mil trace width  / and 10 mil spacing." at 5741,6383 h70
  text "Impedance Tolerance +/-10%" at 5761,6251 h70
  text "All via's are non-tented" at 4895,5391 h50
  text "Symbol" at 4948.5,5183.94 h72
  text "Count" at 5454.38,5183.94 h72
  text "Hole Size" at 6054.22,5183.94 h72
  text "Plated" at 7203.88,5183.94 h72
  text "Hole Type" at 7709.76,5183.94 h72
  text "Routed Path Length" at 8443.56,5183.94 h72
  text "3" at 5454.38,5033.94 h60
  text "7.50mil (0.191mm)" at 6054.22,5033.94 h60
  text "PTH" at 7203.88,5033.94 h60
  text "Round" at 7709.76,5033.94 h60
  text "-" at 8443.56,5033.94 h60
  text "F" at 4919.41,5023.95 h66.67
  text "15" at 5454.38,4883.94 h60
  text "7.87mil (0.200mm)" at 6054.22,4883.94 h60
  text "PTH" at 7203.88,4883.94 h60
  text "Round" at 7709.76,4883.94 h60
  text "-" at 8443.56,4883.94 h60
  text "2" at 5454.38,4733.94 h60
  text "8.00mil (0.203mm)" at 6054.22,4733.94 h60
  text "PTH" at 7203.88,4733.94 h60
  text "Round" at 7709.76,4733.94 h60
  text "-" at 8443.56,4733.94 h60
  text "E" at 4919.41,4723.95 h66.67
  text "30" at 5454.38,4583.94 h60
  text "10.00mil (0.254mm)" at 6054.22,4583.94 h60
  text "PTH" at 7203.88,4583.94 h60
  text "Round" at 7709.76,4583.94 h60
  text "-" at 8443.56,4583.94 h60
  text "537" at 5454.38,4433.94 h60
  text "12.00mil (0.305mm)" at 6054.22,4433.94 h60
  text "PTH" at 7203.88,4433.94 h60
  text "Round" at 7709.76,4433.94 h60
  text "-" at 8443.56,4433.94 h60
  text "2" at 5454.38,4283.94 h60
  text "16.00mil (0.406mm)" at 6054.22,4283.94 h60
  text "PTH" at 7203.88,4283.94 h60
  text "Round" at 7709.76,4283.94 h60
  text "-" at 8443.56,4283.94 h60
  text "O" at 4919.41,4273.95 h66.67
  text "2" at 5454.38,4133.94 h60
  text "19.69mil (0.500mm)" at 6054.22,4133.94 h60
  text "PTH" at 7203.88,4133.94 h60
  text "Slot" at 7709.76,4133.94 h60
  text "25.59mil (0.650mm)" at 8443.56,4133.94 h60
  text "2" at 5454.38,3983.94 h60
  text "21.65mil (0.550mm)" at 6054.22,3983.94 h60
  text "PTH" at 7203.88,3983.94 h60
  text "Slot" at 7709.76,3983.94 h60
  text "11.81mil (0.300mm)" at 8443.56,3983.94 h60
  text "20" at 5454.38,3833.94 h60
  text "27.56mil (0.700mm)" at 6054.22,3833.94 h60
  text "PTH" at 7203.88,3833.94 h60
  text "Round" at 7709.76,3833.94 h60
  text "-" at 8443.56,3833.94 h60
  text "C" at 4919.41,3823.95 h66.67
  text "8" at 5454.38,3683.94 h60
  text "35.04mil (0.890mm)" at 6054.22,3683.94 h60
  text "PTH" at 7203.88,3683.94 h60
  text "Round" at 7709.76,3683.94 h60
  text "-" at 8443.56,3683.94 h60
  text "20" at 5454.38,3533.94 h60
  text "39.37mil (1.000mm)" at 6054.22,3533.94 h60
  text "PTH" at 7203.88,3533.94 h60
  text "Round" at 7709.76,3533.94 h60
  text "-" at 8443.56,3533.94 h60
  text "3" at 5454.38,3383.94 h60
  text "39.37mil (1.000mm)" at 6054.22,3383.94 h60
  text "PTH" at 7203.88,3383.94 h60
  text "Slot" at 7709.76,3383.94 h60
  text "98.43mil (2.500mm)" at 8443.56,3383.94 h60
  text "B" at 4919.41,3373.95 h66.67
  text "68" at 5454.38,3233.94 h60
  text "40.00mil (1.016mm)" at 6054.22,3233.94 h60
  text "PTH" at 7203.88,3233.94 h60
  text "Round" at 7709.76,3233.94 h60
  text "-" at 8443.56,3233.94 h60
  text "38" at 5454.38,3083.94 h60
  text "50.00mil (1.270mm)" at 6054.22,3083.94 h60
  text "PTH" at 7203.88,3083.94 h60
  text "Round" at 7709.76,3083.94 h60
  text "-" at 8443.56,3083.94 h60
  text "2" at 5454.38,2933.94 h60
  text "59.06mil (1.500mm)" at 6054.22,2933.94 h60
  text "PTH" at 7203.88,2933.94 h60
  text "Round" at 7709.76,2933.94 h60
  text "-" at 8443.56,2933.94 h60
  text "2" at 5454.38,2783.94 h60
  text "61.81mil (1.570mm)" at 6054.22,2783.94 h60
  text "PTH" at 7203.88,2783.94 h60
  text "Round" at 7709.76,2783.94 h60
  text "-" at 8443.56,2783.94 h60
  text "8" at 5454.38,2633.94 h60
  text "62.99mil (1.600mm)" at 6054.22,2633.94 h60
  text "PTH" at 7203.88,2633.94 h60
  text "Round" at 7709.76,2633.94 h60
  text "-" at 8443.56,2633.94 h60
  text "4" at 5454.38,2483.94 h60
  text "125.98mil (3.200mm)" at 6054.22,2483.94 h60
  text "PTH" at 7203.88,2483.94 h60
  text "Round" at 7709.76,2483.94 h60
  text "-" at 8443.56,2483.94 h60
  text "A" at 4919.41,2473.95 h66.67
  text "2" at 5454.38,2333.94 h60
  text "128.00mil (3.251mm)" at 6054.22,2333.94 h60
  text "PTH" at 7203.88,2333.94 h60
  text "Round" at 7709.76,2333.94 h60
  text "-" at 8443.56,2333.94 h60
  text "768 Total" at 5454.38,2183.94 h60
  text "Slot definitions :" at 4948.5,2038.97 h60
  text "Routed Path Length" at 5981.19,2038.97 h60
  text "= Calculated from tool start centre position to tool end centre position." at 7083.86,2038.97 h60
  text "Hole Length" at 5981.19,1938.99 h60
  text "= Routed Path Length + Tool Size = Slot length as defined in the PCB layout" at 6673.99,1938.99 h60
  text "Drill Tolerance:" at 5066,1521 h70
  text "For 7.5mil +0/-7.5mil" at 5067,1350.31 h70
  text "For 7.87 mil +0/-7.87 mil" at 5067,1183.42 h70
  text "For 8 mil +0/-8 mil" at 5067,1016.52 h70
  text "For 10 mil +0/-10mil" at 5067,849.62 h70
  text "For 12 mil +0/-12 mil" at 5067,682.72 h70
  text "For 16mil +0/-16 mil" at 5067,515.82 h70
  text "For PTH +/-3 mil" at 5067,348.92 h70
  text "For NPTH +/-2 mil" at 5067,182.02 h70
  text ".Layer_Name" at 577,-1346.68 h60
M17 Embedded Cavity:
  text ".Layer_Name" at 577,-1346.68 h60
M18 Embedded Assembly:
  text ".Layer_Name" at 577,-1346.68 h60
M19 Embedded Keepout:
  text ".Layer_Name" at 577,-1346.68 h60

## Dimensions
0,0 to 4497.63,0 on M2 Board Dimensions
0,0 to 0,4881.81 on M2 Board Dimensions
0,-888.19 to 1000,-888.19 on M2 Board Dimensions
